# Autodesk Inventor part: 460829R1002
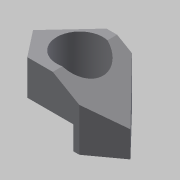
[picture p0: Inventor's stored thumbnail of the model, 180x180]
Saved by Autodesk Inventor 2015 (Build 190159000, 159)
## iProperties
Created: 2016-08
Part Number: 460829R1002
Material: 일반
Document SubType Name: Modeling
Designer: jio
Density: 1 g/cm^3
Appearance: 기본값
Author: jio
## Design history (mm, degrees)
sketch "스케치1"
  geometry: L1 (-70, -10)-(-9.387, 55); L2 (-9.387, 55)-(34, 55); L3 (34, 55)-(104.673, -18.184); L4 (104.673, -18.184)-(54, -55); L5 (54, -55)-(-34.842, -55); L6 (-34.842, -55)-(-70, -10); C1 r 39.5 at (0, 0); 1 further point
  constraints: 12 end point, 2 horizontal, 1 centre point, 1 coincident
  dimensions: "d0" = 79 diameter of C1; "d4" = 99 deg angle of L6 L1; "d5" = 128 deg angle of L5 L6; "d6" = 144 deg angle of L4 L5; "d7" = 134 deg angle of L3 L2; "d8" = 104 horizontal distance of L2.end L1.start; "d9" = 124 horizontal distance of L4.end L1.start; "d10" = 45 vertical distance of L1.start L5.end; "d11" = 110 vertical distance of L1.end L5.end; "d12" = 70 horizontal distance of point (0, 0) L1.start; "d13" = 55 vertical distance of point (0, 0) L5.end
extrude "돌출1" new body sketch "스케치1" distance "d14" = 100; taper "d15" = 0 deg
sketch "스케치3"
  geometry: L1 (-70, 15)-(44, 15); L2 (44, 15)-(44, -55); L3 (44, -55)-(-70, -55); L4 (-70, -55)-(-70, 15); 2 further points
  constraints: 8 end point, 2 parallel, 1 horizontal, 1 perpendicular, 1 point on line
  dimensions: "d18" = 114 distance between parallel lines of L2 L4; "d19" = 55 distance from line of point (0, 0) L3; "d20" = 70 distance between parallel lines of L1 L3
extrude "돌출2" cut sketch "스케치3" distance "d21" = 40; taper "d22" = 0 deg
sketch "스케치4"
  geometry: L1 (0, 0)-(88.842, 0) reference; L2 (43.515, 0)-(139.515, 0); L3 (139.515, 0)-(139.515, -55.426); L4 (139.515, -55.426)-(43.515, 0); 2 further points
  constraints: 6 end point, 1 coincident, 1 horizontal, 1 perpendicular
  dimensions: "d23" = 96 distance of L2.start L2.end; "d24" = 30 deg angle of L4 L1
extrude "돌출3" cut sketch "스케치4" stored distance "d25" = 40; taper "d26" = 0 deg
node "솔리드1"
